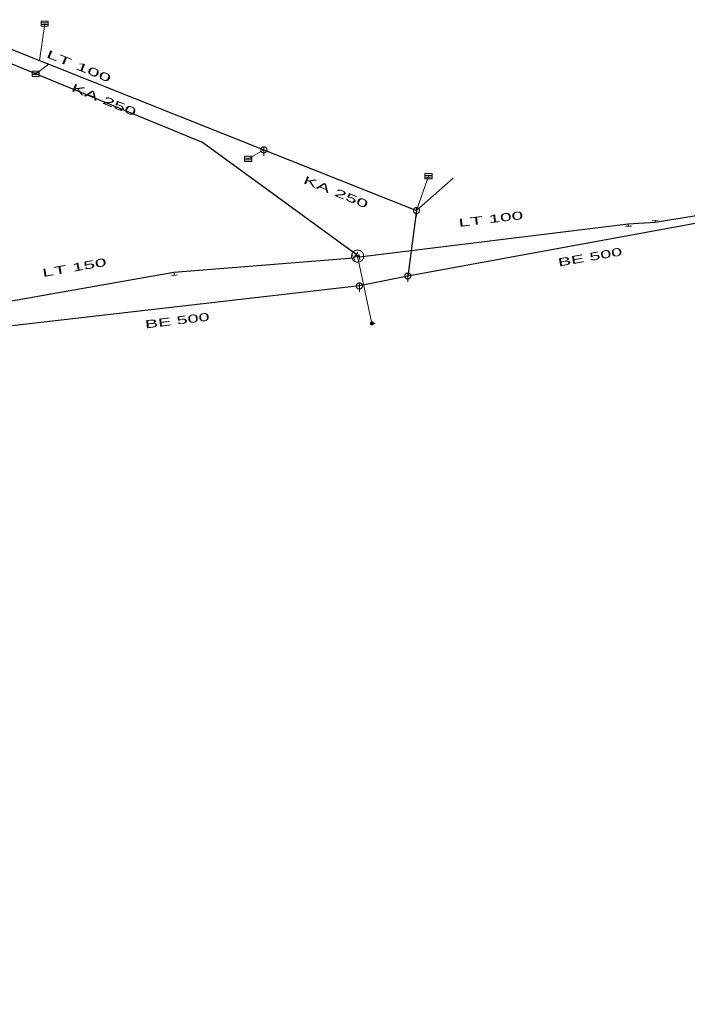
# Model space of a CAD drawing. Extents: x -687515 to -686506, y -974029 to -973461.
# Drawn here: x -686912 to -686856.4, y -973790.3 to -973708.8 of the extents above; entities that cross this region are included whole.
import ezdxf
from ezdxf.enums import TextEntityAlignment as Align

# ---------------------------------------------------------------- set-up
doc = ezdxf.new("R2010")
doc.units = 0
doc.header["$LTSCALE"] = 0.27
for name, color, linetype, lineweight in [('1', 7, 'Continuous', 13), ('11', 7, 'Continuous', 13), ('14', 7, 'Continuous', 25), ('17', 7, 'Continuous', 25), ('22', 7, 'Continuous', 13), ('34', 7, 'Continuous', 13), ('47', 7, 'Continuous', 13), ('9', 7, 'Continuous', 13)]:
    doc.layers.add(name, color=color, linetype=linetype, lineweight=lineweight)

msp = doc.modelspace()

# ---------------------------------------------------------------- linework, layer by layer
at = {"layer": '11'}
for p, q in [((-686909.91, -973709.12), (-686910.34, -973712.19)), ((-686910.66, -973713.29), (-686909.57, -973712.49)), ((-686892.97, -973720.38), (-686891.67, -973719.62)), ((-686877.96, -973721.82), (-686878.96, -973724.68)), ((-686875.89, -973721.97), (-686878.96, -973724.68))]:
    msp.add_line(p, q, dxfattribs=at)
at = {"layer": '14'}
for p, q in [((-686891.67, -973719.62), (-686878.96, -973724.68)), ((-686849.73, -973724.67), (-686879.68, -973730.129)), ((-686878.96, -973724.68), (-686879.68, -973730.129)), ((-686879.68, -973730.129), (-686883.71, -973730.96)), ((-686883.71, -973730.96), (-686914.257, -973734.469))]:
    msp.add_line(p, q, dxfattribs=at)
at = {"layer": '14', "lineweight": 13}
for p, q in [((-686861.337, -973725.804), (-686861.299, -973725.979)), ((-686859.074, -973725.682), (-686859.089, -973725.5)), ((-686883.855, -973728.474), (-686884.189, -973728.62)), ((-686883.855, -973728.474), (-686882.671, -973734.074)), ((-686899.151, -973729.811), (-686899.109, -973730.079))]:
    msp.add_line(p, q, dxfattribs=at)
at = {"layer": '14'}
msp.add_lwpolyline([(-686917.57, -973709.309), (-686910.34, -973712.19), (-686909.57, -973712.489), (-686891.67, -973719.62)], dxfattribs=at)
at = {"layer": '14', "lineweight": 13}
msp.add_lwpolyline([(-686883.709, -973728.57), (-686883.855, -973728.474), (-686883.979, -973728.339)], dxfattribs=at)
at = {"layer": '17'}
for points in [[(-686883.979, -973728.339), (-686896.774, -973719.019), (-686918.904, -973709.9), (-686935.168, -973708.778), (-686948.922, -973714.994)], [(-686778.16, -973716.008), (-686787.234, -973721.504), (-686796.6, -973724.188), (-686817.64, -973721.881), (-686819.859, -973721.829), (-686837.05, -973722.085), (-686859.074, -973725.682), (-686861.337, -973725.804), (-686883.709, -973728.57)], [(-686976.761, -973790.276), (-686962.561, -973784.848), (-686950.728, -973778.526), (-686943.195, -973771.934), (-686939.23, -973761.912), (-686935.397, -973746.442), (-686925.984, -973737.294), (-686915.07, -973732.61), (-686899.151, -973729.811), (-686884.189, -973728.62)]]:
    msp.add_lwpolyline(points, dxfattribs=at)
at = {"layer": '22'}
for p, q in [((-686910.205, -973709.049), (-686909.607, -973709.049)), ((-686910.205, -973709.195), (-686909.607, -973709.195)), ((-686910.955, -973713.218), (-686910.357, -973713.218)), ((-686910.955, -973713.364), (-686910.357, -973713.364)), ((-686891.669, -973719.368), (-686891.67, -973720.112)), ((-686893.264, -973720.308), (-686892.666, -973720.308)), ((-686893.264, -973720.453), (-686892.666, -973720.453)), ((-686878.255, -973721.749), (-686877.657, -973721.749)), ((-686878.255, -973721.894), (-686877.657, -973721.894)), ((-686878.959, -973724.428), (-686878.96, -973725.172)), ((-686879.679, -973729.878), (-686879.68, -973730.622)), ((-686883.709, -973730.708), (-686883.71, -973731.451))]:
    msp.add_line(p, q, dxfattribs=at)
for points in [[(-686910.205, -973708.903), (-686909.607, -973708.903), (-686909.607, -973709.34), (-686910.205, -973709.34)], [(-686910.955, -973713.072), (-686910.357, -973713.072), (-686910.357, -973713.509), (-686910.955, -973713.509)], [(-686893.264, -973720.162), (-686892.666, -973720.162), (-686892.666, -973720.598), (-686893.264, -973720.598)], [(-686891.418, -973719.62), (-686891.419, -973719.594), (-686891.423, -973719.568), (-686891.429, -973719.542), (-686891.439, -973719.518), (-686891.451, -973719.494), (-686891.465, -973719.472), (-686891.482, -973719.451), (-686891.5, -973719.433), (-686891.521, -973719.416), (-686891.543, -973719.402), (-686891.567, -973719.39), (-686891.591, -973719.38), (-686891.617, -973719.374), (-686891.643, -973719.37), (-686891.669, -973719.368), (-686891.695, -973719.369), (-686891.721, -973719.373), (-686891.747, -973719.379), (-686891.772, -973719.389), (-686891.795, -973719.401), (-686891.817, -973719.415), (-686891.838, -973719.432), (-686891.856, -973719.45), (-686891.873, -973719.471), (-686891.887, -973719.493), (-686891.899, -973719.517), (-686891.909, -973719.541), (-686891.916, -973719.567), (-686891.92, -973719.593), (-686891.922, -973719.619), (-686891.921, -973719.645), (-686891.917, -973719.671), (-686891.91, -973719.697), (-686891.9, -973719.722), (-686891.888, -973719.745), (-686891.874, -973719.767), (-686891.857, -973719.788), (-686891.839, -973719.806), (-686891.818, -973719.823), (-686891.796, -973719.837), (-686891.773, -973719.849), (-686891.748, -973719.859), (-686891.722, -973719.866), (-686891.696, -973719.87), (-686891.67, -973719.872), (-686891.644, -973719.871), (-686891.618, -973719.867), (-686891.592, -973719.86), (-686891.568, -973719.85), (-686891.544, -973719.838), (-686891.522, -973719.824), (-686891.501, -973719.807), (-686891.483, -973719.789), (-686891.466, -973719.768), (-686891.452, -973719.746), (-686891.44, -973719.723), (-686891.43, -973719.698), (-686891.424, -973719.672), (-686891.42, -973719.646)], [(-686878.255, -973721.603), (-686877.657, -973721.603), (-686877.657, -973722.039), (-686878.255, -973722.039)], [(-686878.708, -973724.68), (-686878.709, -973724.654), (-686878.713, -973724.628), (-686878.719, -973724.602), (-686878.729, -973724.578), (-686878.741, -973724.554), (-686878.755, -973724.532), (-686878.772, -973724.511), (-686878.79, -973724.493), (-686878.811, -973724.476), (-686878.833, -973724.462), (-686878.857, -973724.45), (-686878.881, -973724.44), (-686878.907, -973724.434), (-686878.933, -973724.43), (-686878.959, -973724.428), (-686878.985, -973724.429), (-686879.011, -973724.433), (-686879.037, -973724.439), (-686879.062, -973724.449), (-686879.085, -973724.461), (-686879.107, -973724.475), (-686879.128, -973724.492), (-686879.146, -973724.51), (-686879.163, -973724.531), (-686879.177, -973724.553), (-686879.189, -973724.577), (-686879.199, -973724.601), (-686879.206, -973724.627), (-686879.21, -973724.653), (-686879.212, -973724.679), (-686879.211, -973724.705), (-686879.207, -973724.731), (-686879.2, -973724.757), (-686879.19, -973724.782), (-686879.178, -973724.805), (-686879.164, -973724.827), (-686879.147, -973724.848), (-686879.129, -973724.866), (-686879.108, -973724.883), (-686879.086, -973724.897), (-686879.063, -973724.909), (-686879.038, -973724.919), (-686879.012, -973724.926), (-686878.986, -973724.93), (-686878.96, -973724.932), (-686878.934, -973724.931), (-686878.908, -973724.927), (-686878.882, -973724.92), (-686878.858, -973724.91), (-686878.834, -973724.898), (-686878.812, -973724.884), (-686878.791, -973724.867), (-686878.773, -973724.849), (-686878.756, -973724.828), (-686878.742, -973724.806), (-686878.73, -973724.783), (-686878.72, -973724.758), (-686878.714, -973724.732), (-686878.71, -973724.706)], [(-686879.428, -973730.13), (-686879.429, -973730.104), (-686879.433, -973730.078), (-686879.439, -973730.052), (-686879.449, -973730.028), (-686879.461, -973730.004), (-686879.475, -973729.982), (-686879.492, -973729.961), (-686879.51, -973729.943), (-686879.531, -973729.926), (-686879.553, -973729.912), (-686879.577, -973729.9), (-686879.601, -973729.89), (-686879.627, -973729.884), (-686879.653, -973729.88), (-686879.679, -973729.878), (-686879.705, -973729.879), (-686879.731, -973729.883), (-686879.757, -973729.889), (-686879.782, -973729.899), (-686879.805, -973729.911), (-686879.827, -973729.925), (-686879.848, -973729.942), (-686879.866, -973729.96), (-686879.883, -973729.981), (-686879.897, -973730.003), (-686879.909, -973730.027), (-686879.919, -973730.051), (-686879.926, -973730.077), (-686879.93, -973730.103), (-686879.932, -973730.129), (-686879.931, -973730.155), (-686879.927, -973730.181), (-686879.92, -973730.207), (-686879.91, -973730.232), (-686879.898, -973730.255), (-686879.884, -973730.277), (-686879.867, -973730.298), (-686879.849, -973730.316), (-686879.828, -973730.333), (-686879.806, -973730.347), (-686879.783, -973730.359), (-686879.758, -973730.369), (-686879.732, -973730.376), (-686879.706, -973730.38), (-686879.68, -973730.382), (-686879.654, -973730.381), (-686879.628, -973730.377), (-686879.602, -973730.37), (-686879.578, -973730.36), (-686879.554, -973730.348), (-686879.532, -973730.334), (-686879.511, -973730.317), (-686879.493, -973730.299), (-686879.476, -973730.278), (-686879.462, -973730.256), (-686879.45, -973730.233), (-686879.44, -973730.208), (-686879.434, -973730.182), (-686879.43, -973730.156)], [(-686883.458, -973730.96), (-686883.459, -973730.934), (-686883.463, -973730.908), (-686883.469, -973730.882), (-686883.479, -973730.858), (-686883.491, -973730.834), (-686883.505, -973730.812), (-686883.522, -973730.791), (-686883.54, -973730.773), (-686883.561, -973730.756), (-686883.583, -973730.742), (-686883.607, -973730.73), (-686883.631, -973730.72), (-686883.657, -973730.714), (-686883.683, -973730.71), (-686883.709, -973730.708), (-686883.735, -973730.709), (-686883.761, -973730.713), (-686883.787, -973730.719), (-686883.812, -973730.729), (-686883.835, -973730.741), (-686883.857, -973730.755), (-686883.878, -973730.772), (-686883.896, -973730.79), (-686883.913, -973730.811), (-686883.927, -973730.833), (-686883.939, -973730.857), (-686883.949, -973730.881), (-686883.956, -973730.907), (-686883.96, -973730.933), (-686883.962, -973730.959), (-686883.961, -973730.985), (-686883.957, -973731.011), (-686883.95, -973731.037), (-686883.94, -973731.062), (-686883.928, -973731.085), (-686883.914, -973731.107), (-686883.897, -973731.128), (-686883.879, -973731.146), (-686883.858, -973731.163), (-686883.836, -973731.177), (-686883.813, -973731.189), (-686883.788, -973731.199), (-686883.762, -973731.206), (-686883.736, -973731.21), (-686883.71, -973731.212), (-686883.684, -973731.211), (-686883.658, -973731.207), (-686883.632, -973731.2), (-686883.608, -973731.19), (-686883.584, -973731.178), (-686883.562, -973731.164), (-686883.541, -973731.147), (-686883.523, -973731.129), (-686883.506, -973731.108), (-686883.492, -973731.086), (-686883.48, -973731.063), (-686883.47, -973731.038), (-686883.464, -973731.012), (-686883.46, -973730.986)]]:
    msp.add_lwpolyline(points, close=True, dxfattribs=at)
at = {"layer": '34'}
for p, q in [((-686859.336, -973725.511), (-686858.841, -973725.488)), ((-686861.051, -973725.99), (-686861.546, -973725.967)), ((-686884.119, -973728.543), (-686883.838, -973728.134)), ((-686883.677, -973728.815), (-686883.74, -973728.324)), ((-686884.089, -973728.847), (-686884.288, -973728.392)), ((-686899.354, -973730.116), (-686898.863, -973730.041))]:
    msp.add_line(p, q, dxfattribs=at)
at = {"layer": '47'}
for points in [[(-686883.356, -973728.474), (-686883.359, -973728.422), (-686883.367, -973728.37), (-686883.381, -973728.32), (-686883.399, -973728.271), (-686883.423, -973728.224), (-686883.452, -973728.18), (-686883.485, -973728.14), (-686883.522, -973728.103), (-686883.562, -973728.07), (-686883.606, -973728.041), (-686883.653, -973728.017), (-686883.702, -973727.999), (-686883.752, -973727.985), (-686883.804, -973727.977), (-686883.856, -973727.974), (-686883.908, -973727.977), (-686883.96, -973727.985), (-686884.011, -973727.999), (-686884.059, -973728.017), (-686884.106, -973728.041), (-686884.15, -973728.07), (-686884.191, -973728.103), (-686884.228, -973728.14), (-686884.261, -973728.18), (-686884.289, -973728.224), (-686884.313, -973728.271), (-686884.332, -973728.32), (-686884.345, -973728.37), (-686884.353, -973728.422), (-686884.356, -973728.474), (-686884.353, -973728.526), (-686884.345, -973728.578), (-686884.332, -973728.629), (-686884.313, -973728.677), (-686884.289, -973728.724), (-686884.261, -973728.768), (-686884.228, -973728.809), (-686884.191, -973728.846), (-686884.15, -973728.879), (-686884.106, -973728.907), (-686884.059, -973728.931), (-686884.011, -973728.95), (-686883.96, -973728.963), (-686883.908, -973728.971), (-686883.856, -973728.974), (-686883.804, -973728.971), (-686883.752, -973728.963), (-686883.702, -973728.95), (-686883.653, -973728.931), (-686883.606, -973728.907), (-686883.562, -973728.879), (-686883.522, -973728.846), (-686883.485, -973728.809), (-686883.452, -973728.768), (-686883.423, -973728.724), (-686883.399, -973728.677), (-686883.381, -973728.629), (-686883.367, -973728.578), (-686883.359, -973728.526)], [(-686883.774, -973728.474), (-686883.774, -973728.465), (-686883.776, -973728.457), (-686883.778, -973728.449), (-686883.781, -973728.441), (-686883.785, -973728.433), (-686883.79, -973728.426), (-686883.795, -973728.419), (-686883.801, -973728.413), (-686883.808, -973728.408), (-686883.815, -973728.403), (-686883.823, -973728.399), (-686883.831, -973728.396), (-686883.839, -973728.394), (-686883.847, -973728.392), (-686883.856, -973728.392), (-686883.865, -973728.392), (-686883.873, -973728.394), (-686883.881, -973728.396), (-686883.889, -973728.399), (-686883.897, -973728.403), (-686883.904, -973728.408), (-686883.911, -973728.413), (-686883.917, -973728.419), (-686883.923, -973728.426), (-686883.927, -973728.433), (-686883.931, -973728.441), (-686883.934, -973728.449), (-686883.936, -973728.457), (-686883.938, -973728.465), (-686883.938, -973728.474), (-686883.938, -973728.483), (-686883.936, -973728.491), (-686883.934, -973728.499), (-686883.931, -973728.507), (-686883.927, -973728.515), (-686883.923, -973728.522), (-686883.917, -973728.529), (-686883.911, -973728.535), (-686883.904, -973728.541), (-686883.897, -973728.545), (-686883.889, -973728.549), (-686883.881, -973728.552), (-686883.873, -973728.554), (-686883.865, -973728.556), (-686883.856, -973728.556), (-686883.847, -973728.556), (-686883.839, -973728.554), (-686883.831, -973728.552), (-686883.823, -973728.549), (-686883.815, -973728.545), (-686883.808, -973728.541), (-686883.801, -973728.535), (-686883.795, -973728.529), (-686883.79, -973728.522), (-686883.785, -973728.515), (-686883.781, -973728.507), (-686883.778, -973728.499), (-686883.776, -973728.491), (-686883.774, -973728.483)]]:
    msp.add_lwpolyline(points, close=True, dxfattribs=at)
at = {"layer": '9'}
msp.add_line((-686882.544, -973734.074), (-686882.419, -973734.074), dxfattribs=at)
for points in [[(-686882.671, -973734.2), (-686882.658, -973734.199), (-686882.645, -973734.197), (-686882.632, -973734.194), (-686882.62, -973734.189), (-686882.608, -973734.183), (-686882.597, -973734.176), (-686882.587, -973734.168), (-686882.577, -973734.158), (-686882.569, -973734.148), (-686882.562, -973734.137), (-686882.556, -973734.125), (-686882.551, -973734.113), (-686882.548, -973734.1), (-686882.546, -973734.087), (-686882.544, -973734.074), (-686882.545, -973734.061), (-686882.547, -973734.048), (-686882.55, -973734.035), (-686882.555, -973734.023), (-686882.561, -973734.011), (-686882.568, -973734), (-686882.576, -973733.99), (-686882.586, -973733.98), (-686882.596, -973733.972), (-686882.607, -973733.965), (-686882.619, -973733.959), (-686882.631, -973733.954), (-686882.644, -973733.951), (-686882.657, -973733.949), (-686882.67, -973733.948), (-686882.683, -973733.948), (-686882.696, -973733.95), (-686882.709, -973733.953), (-686882.721, -973733.958), (-686882.733, -973733.964), (-686882.744, -973733.971), (-686882.754, -973733.979), (-686882.764, -973733.989), (-686882.772, -973733.999), (-686882.779, -973734.01), (-686882.785, -973734.022), (-686882.79, -973734.034), (-686882.793, -973734.047), (-686882.795, -973734.06), (-686882.797, -973734.073), (-686882.796, -973734.086), (-686882.794, -973734.099), (-686882.791, -973734.112), (-686882.786, -973734.124), (-686882.78, -973734.136), (-686882.773, -973734.147), (-686882.765, -973734.157), (-686882.755, -973734.167), (-686882.745, -973734.175), (-686882.734, -973734.182), (-686882.722, -973734.188), (-686882.71, -973734.193), (-686882.697, -973734.196), (-686882.684, -973734.198)], [(-686882.671, -973734.18), (-686882.66, -973734.18), (-686882.649, -973734.178), (-686882.638, -973734.175), (-686882.628, -973734.171), (-686882.618, -973734.166), (-686882.609, -973734.16), (-686882.6, -973734.153), (-686882.592, -973734.145), (-686882.585, -973734.136), (-686882.579, -973734.127), (-686882.574, -973734.117), (-686882.57, -973734.107), (-686882.567, -973734.096), (-686882.565, -973734.085), (-686882.565, -973734.074), (-686882.564, -973734.063), (-686882.566, -973734.052), (-686882.569, -973734.041), (-686882.573, -973734.031), (-686882.578, -973734.021), (-686882.584, -973734.012), (-686882.591, -973734.003), (-686882.599, -973733.995), (-686882.608, -973733.988), (-686882.617, -973733.982), (-686882.627, -973733.977), (-686882.637, -973733.973), (-686882.648, -973733.97), (-686882.659, -973733.968), (-686882.67, -973733.968), (-686882.681, -973733.967), (-686882.692, -973733.969), (-686882.703, -973733.972), (-686882.713, -973733.976), (-686882.723, -973733.981), (-686882.732, -973733.987), (-686882.741, -973733.994), (-686882.749, -973734.002), (-686882.756, -973734.011), (-686882.762, -973734.02), (-686882.767, -973734.03), (-686882.771, -973734.04), (-686882.774, -973734.051), (-686882.776, -973734.062), (-686882.777, -973734.073), (-686882.777, -973734.084), (-686882.775, -973734.095), (-686882.772, -973734.106), (-686882.768, -973734.116), (-686882.763, -973734.126), (-686882.757, -973734.135), (-686882.75, -973734.144), (-686882.742, -973734.152), (-686882.733, -973734.159), (-686882.724, -973734.165), (-686882.714, -973734.17), (-686882.704, -973734.174), (-686882.693, -973734.177), (-686882.682, -973734.179)], [(-686882.671, -973734.161), (-686882.662, -973734.16), (-686882.653, -973734.159), (-686882.644, -973734.156), (-686882.636, -973734.153), (-686882.628, -973734.149), (-686882.62, -973734.144), (-686882.613, -973734.138), (-686882.607, -973734.132), (-686882.601, -973734.125), (-686882.596, -973734.117), (-686882.592, -973734.109), (-686882.589, -973734.101), (-686882.586, -973734.092), (-686882.585, -973734.083), (-686882.583, -973734.074), (-686882.584, -973734.065), (-686882.585, -973734.056), (-686882.588, -973734.047), (-686882.591, -973734.039), (-686882.595, -973734.031), (-686882.6, -973734.023), (-686882.606, -973734.016), (-686882.612, -973734.01), (-686882.619, -973734.004), (-686882.627, -973733.999), (-686882.635, -973733.995), (-686882.643, -973733.992), (-686882.652, -973733.989), (-686882.661, -973733.988), (-686882.67, -973733.987), (-686882.679, -973733.987), (-686882.688, -973733.988), (-686882.697, -973733.991), (-686882.705, -973733.994), (-686882.713, -973733.998), (-686882.721, -973734.003), (-686882.728, -973734.009), (-686882.734, -973734.015), (-686882.74, -973734.022), (-686882.745, -973734.03), (-686882.749, -973734.038), (-686882.752, -973734.046), (-686882.755, -973734.055), (-686882.756, -973734.064), (-686882.758, -973734.073), (-686882.757, -973734.082), (-686882.756, -973734.091), (-686882.753, -973734.1), (-686882.75, -973734.108), (-686882.746, -973734.116), (-686882.741, -973734.124), (-686882.735, -973734.131), (-686882.729, -973734.137), (-686882.722, -973734.143), (-686882.714, -973734.148), (-686882.706, -973734.152), (-686882.698, -973734.155), (-686882.689, -973734.158), (-686882.68, -973734.159)], [(-686882.671, -973734.141), (-686882.664, -973734.141), (-686882.657, -973734.139), (-686882.65, -973734.138), (-686882.644, -973734.135), (-686882.638, -973734.132), (-686882.632, -973734.128), (-686882.626, -973734.124), (-686882.621, -973734.119), (-686882.617, -973734.113), (-686882.613, -973734.107), (-686882.61, -973734.101), (-686882.607, -973734.095), (-686882.606, -973734.088), (-686882.604, -973734.081), (-686882.603, -973734.074), (-686882.603, -973734.067), (-686882.605, -973734.06), (-686882.606, -973734.053), (-686882.609, -973734.047), (-686882.612, -973734.04), (-686882.616, -973734.035), (-686882.62, -973734.029), (-686882.625, -973734.024), (-686882.631, -973734.02), (-686882.637, -973734.016), (-686882.643, -973734.013), (-686882.649, -973734.01), (-686882.656, -973734.008), (-686882.663, -973734.007), (-686882.67, -973734.007), (-686882.677, -973734.006), (-686882.684, -973734.007), (-686882.691, -973734.009), (-686882.697, -973734.012), (-686882.704, -973734.015), (-686882.709, -973734.019), (-686882.715, -973734.023), (-686882.72, -973734.028), (-686882.724, -973734.034), (-686882.728, -973734.039), (-686882.731, -973734.046), (-686882.734, -973734.052), (-686882.736, -973734.059), (-686882.737, -973734.066), (-686882.738, -973734.073), (-686882.738, -973734.08), (-686882.737, -973734.087), (-686882.735, -973734.094), (-686882.732, -973734.1), (-686882.729, -973734.106), (-686882.725, -973734.112), (-686882.721, -973734.118), (-686882.716, -973734.123), (-686882.71, -973734.127), (-686882.705, -973734.131), (-686882.698, -973734.134), (-686882.692, -973734.137), (-686882.685, -973734.138), (-686882.678, -973734.14)], [(-686882.671, -973734.121), (-686882.666, -973734.121), (-686882.661, -973734.12), (-686882.656, -973734.119), (-686882.652, -973734.117), (-686882.647, -973734.115), (-686882.643, -973734.112), (-686882.64, -973734.109), (-686882.636, -973734.105), (-686882.633, -973734.102), (-686882.63, -973734.098), (-686882.628, -973734.093), (-686882.626, -973734.089), (-686882.625, -973734.084), (-686882.624, -973734.079), (-686882.624, -973734.074), (-686882.623, -973734.069), (-686882.624, -973734.064), (-686882.625, -973734.059), (-686882.627, -973734.055), (-686882.629, -973734.05), (-686882.632, -973734.046), (-686882.635, -973734.042), (-686882.639, -973734.039), (-686882.642, -973734.036), (-686882.646, -973734.033), (-686882.651, -973734.031), (-686882.655, -973734.029), (-686882.66, -973734.028), (-686882.665, -973734.027), (-686882.67, -973734.027), (-686882.675, -973734.026), (-686882.68, -973734.027), (-686882.685, -973734.028), (-686882.689, -973734.03), (-686882.694, -973734.032), (-686882.698, -973734.035), (-686882.702, -973734.038), (-686882.705, -973734.041), (-686882.708, -973734.045), (-686882.711, -973734.049), (-686882.713, -973734.054), (-686882.715, -973734.058), (-686882.716, -973734.063), (-686882.717, -973734.068), (-686882.718, -973734.073), (-686882.718, -973734.078), (-686882.717, -973734.083), (-686882.716, -973734.088), (-686882.714, -973734.092), (-686882.712, -973734.097), (-686882.709, -973734.101), (-686882.706, -973734.104), (-686882.703, -973734.108), (-686882.699, -973734.111), (-686882.695, -973734.114), (-686882.69, -973734.116), (-686882.686, -973734.118), (-686882.681, -973734.119), (-686882.676, -973734.12)], [(-686882.671, -973734.101), (-686882.668, -973734.101), (-686882.665, -973734.101), (-686882.663, -973734.1), (-686882.66, -973734.099), (-686882.657, -973734.098), (-686882.655, -973734.096), (-686882.653, -973734.094), (-686882.651, -973734.092), (-686882.649, -973734.09), (-686882.647, -973734.088), (-686882.646, -973734.085), (-686882.645, -973734.082), (-686882.644, -973734.08), (-686882.644, -973734.077), (-686882.644, -973734.074), (-686882.643, -973734.071), (-686882.643, -973734.068), (-686882.644, -973734.065), (-686882.645, -973734.063), (-686882.646, -973734.06), (-686882.648, -973734.058), (-686882.65, -973734.055), (-686882.652, -973734.053), (-686882.654, -973734.052), (-686882.656, -973734.05), (-686882.659, -973734.049), (-686882.662, -973734.048), (-686882.664, -973734.047), (-686882.667, -973734.047), (-686882.67, -973734.046), (-686882.673, -973734.046), (-686882.676, -973734.046), (-686882.679, -973734.047), (-686882.681, -973734.048), (-686882.684, -973734.049), (-686882.686, -973734.051), (-686882.689, -973734.052), (-686882.691, -973734.054), (-686882.692, -973734.057), (-686882.694, -973734.059), (-686882.695, -973734.062), (-686882.696, -973734.064), (-686882.697, -973734.067), (-686882.697, -973734.07), (-686882.699, -973734.073), (-686882.698, -973734.076), (-686882.698, -973734.079), (-686882.697, -973734.081), (-686882.696, -973734.084), (-686882.695, -973734.087), (-686882.693, -973734.089), (-686882.692, -973734.091), (-686882.69, -973734.093), (-686882.687, -973734.095), (-686882.685, -973734.097), (-686882.682, -973734.098), (-686882.68, -973734.099), (-686882.677, -973734.1), (-686882.674, -973734.1)], [(-686882.671, -973734.082), (-686882.67, -973734.082), (-686882.669, -973734.082), (-686882.669, -973734.081), (-686882.668, -973734.081), (-686882.667, -973734.081), (-686882.666, -973734.08), (-686882.666, -973734.08), (-686882.665, -973734.079), (-686882.665, -973734.079), (-686882.664, -973734.078), (-686882.664, -973734.077), (-686882.664, -973734.076), (-686882.663, -973734.076), (-686882.663, -973734.075), (-686882.663, -973734.074), (-686882.663, -973734.073), (-686882.663, -973734.072), (-686882.663, -973734.072), (-686882.663, -973734.071), (-686882.663, -973734.07), (-686882.664, -973734.069), (-686882.664, -973734.069), (-686882.665, -973734.068), (-686882.665, -973734.068), (-686882.666, -973734.067), (-686882.667, -973734.067), (-686882.668, -973734.066), (-686882.668, -973734.066), (-686882.669, -973734.066), (-686882.67, -973734.066), (-686882.671, -973734.066), (-686882.672, -973734.066), (-686882.672, -973734.066), (-686882.673, -973734.066), (-686882.674, -973734.066), (-686882.675, -973734.067), (-686882.675, -973734.067), (-686882.676, -973734.068), (-686882.676, -973734.068), (-686882.677, -973734.069), (-686882.677, -973734.07), (-686882.678, -973734.071), (-686882.678, -973734.071), (-686882.678, -973734.072), (-686882.679, -973734.073), (-686882.679, -973734.074), (-686882.679, -973734.075), (-686882.679, -973734.075), (-686882.678, -973734.076), (-686882.678, -973734.077), (-686882.677, -973734.078), (-686882.677, -973734.078), (-686882.676, -973734.079), (-686882.676, -973734.079), (-686882.675, -973734.08), (-686882.674, -973734.08), (-686882.673, -973734.08), (-686882.673, -973734.081), (-686882.672, -973734.081)]]:
    msp.add_lwpolyline(points, close=True, dxfattribs=at)
msp.add_lwpolyline([(-686882.453, -973734.043), (-686882.419, -973734.074), (-686882.454, -973734.105)], dxfattribs=at)

# ---------------------------------------------------------------- texts
at = {"layer": '1'}
for s, rotation, width, p in [('LT 100', 338, 2.05, (-686907.191, -973712.965)), ('KA 250', 338, 1.95, (-686905.099, -973715.765)), ('KA 250', 338, 1.95, (-686885.794, -973723.449)), ('LT 100', 7, 1.95, (-686872.725, -973725.712)), ('BE 500', 10, 1.85, (-686864.451, -973728.873)), ('LT 150', 10, 1.95, (-686907.384, -973729.743)), ('BE 500', 7, 1.85, (-686898.837, -973734.166))]:
    msp.add_text(s, height=0.6667, rotation=rotation, dxfattribs=dict(at, width=width)).set_placement(p, align=Align.CENTER)

doc.saveas('drawing.dxf')
